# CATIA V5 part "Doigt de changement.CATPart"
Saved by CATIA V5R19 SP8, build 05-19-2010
Part number: Doigt de changement
Bounding box of the stored display mesh (mm): x 0 to 20, y -70.483 to 16.59, z -33.519 to 15
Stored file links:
  F:\CFAO\Hberriche\Doigt de changement.CATPart
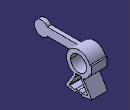
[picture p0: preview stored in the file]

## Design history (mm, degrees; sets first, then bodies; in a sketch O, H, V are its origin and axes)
Body1 (main body)
  Sketch1 on yz-plane, origin (0, 0, 0), H (0, 1, 0), V (0, 0, 1)
    circle A1 centre (0, 0) radius 10
    circle A2 centre (0, 0) radius 15
    radius A1 = 10
    radius A2 = 15
  Pad1: profile Sketch1, direction (1, 0, 0), length 20
  Plane1: type Offset, RefPlane zx-plane, Offset 14
  Sketch2 on Plane1, origin (0, 14, 0), H (-1, 0, 0), V (0, 0, 1)
    point P1 (0, 5)
    line L1 (0, 5) -> (-20, 5)
    line L2 (-20, 5) -> (-20, -5)
    line L3 (-20, -5) -> (0, -5)
    line L4 (0, -5) -> (0, 5)
    reference projected line E1 (-20, -10) -> (-20, 10) from edge [end face of Pad1 | face of Pad1 from Sketch1.A1]
    reference projected line E2 through (0, 0) direction (-1, 0) from axis of face of Pad1 from Sketch1.A2
    length L4 = 10
    distance L1 E2 = 5
    coincidence: P1 V, E1 L2
    horizontal: L1 H, L3 H
    vertical: L2 V, L4 V
  Pad2: profile Sketch2, direction (0, 1, 0), length 2
  Sketch3 on face of Pad2, origin (20, 0, 0), H (0, 1, 0), V (0, 0, 1)
    point P1 (-6.4761, -11.7933)
    line L1 (-6.4761, -11.7933) -> (-6.4761, -14.6103)
    point P2 (-6.4761, -14.6103)
    line L2 (-6.4761, -14.6103) -> (-16.5902, -31.3039)
    point P3 (-16.5902, -31.3039)
    axis line L3 (0, 20.9659) -> (0, -37.2678)
    point P4 (0, 20.9659)
    point P5 (0, -37.2678)
    line L4 (-6.4761, -11.7933) -> (0, -11.7933)
    point P6 (0, -11.7933)
    line L5 (-16.5902, -31.3039) -> (-5.1041, -33.5191)
    point P7 (-5.1041, -33.5191)
    arc A1 centre (0, -37.4647) radius 6.4513 from (0, -31.0134) to (-5.1041, -33.5191) ccw
    point P8 (0, -37.4647)
    point P9 (-5.1041, -33.5191)
    point P10 (0, -31.0134)
    point P11 (6.4761, -11.7933)
    point P12 (6.4761, -14.6103)
    point P13 (16.5902, -31.3039)
    point P14 (0, -37.2678)
    point P15 (0, -11.7933)
    point P16 (5.1041, -33.5191)
    point P18 (5.1041, -33.5191)
    point P19 (0, -31.0134)
    line L6 (6.4761, -11.7933) -> (6.4761, -14.6103)
    line L7 (6.4761, -14.6103) -> (16.5902, -31.3039)
    line L8 (6.4761, -11.7933) -> (0, -11.7933)
    line L9 (16.5902, -31.3039) -> (5.1041, -33.5191)
    arc A2 centre (0, -37.4647) radius 6.4513 from (0, -31.0134) to (5.1041, -33.5191) cw
    vertical: L1 V, L3 V
    coincidence: P4 V, P6 L3, P9 L5, P10 L3, P7 P9, P8 L3, P6 P15, P10 P19, P16 P18
    horizontal: L4 H
    symmetry: P1 P11 L3, P2 P12 L3, P3 P13 L3, P5 P14 L3, P6 P15 L3, P7 P16 L3, P9 P18 L3, P10 P19 L3, L1 L6 L3, L2 L7 L3, L4 L8 L3, L5 L9 L3, A1 A2 L3
  Pad3: profile Sketch3, direction (-1, 0, 0), length 20
  Sketch4 on face of Pad3, origin (20, 0, 0), H (0, 1, 0), V (0, 0, 1)
    axis line L1 (0, -45.8809) -> (0, -7.9795)
    point P1 (0, -45.8809)
    point P2 (0, -7.9795)
    line L2 (0, -12.3129) -> (-3, -12.3129)
    point P3 (0, -12.3129)
    point P4 (-4, -12.3129)
    line L3 (-4, -13.3129) -> (-4, -14.9164)
    point P5 (-4, -16.3129)
    line L4 (-4.7236, -17.5073) -> (-11.42, -28.5599)
    line L5 (-11.0871, -29.31) -> (-4.6321, -30.5548)
    point P6 (-4.6321, -30.5548)
    arc A1 centre (0, -37.7651) radius 8.57 from (0, -29.1951) to (-4.6321, -30.5548) ccw
    point P7 (0, -37.7651)
    point P8 (0, -29.1951)
    reference projected line E1 (-6.4761, -14.6103) -> (-16.5902, -31.3039) from edge [face of Pad3 from Sketch3.L2 | start face of Pad3]
    reference projected line E2 (-16.5902, -31.3039) -> (-5.1041, -33.5191) from edge [face of Pad3 from Sketch3.L5 | start face of Pad3]
    arc A2 centre (-10.9924, -28.819) radius 0.5 from (-11.42, -28.5599) to (-11.0871, -29.31) ccw
    point P9 (-11.42, -28.5599)
    point P10 (-11.0871, -29.31)
    arc A3 centre (-3, -13.3129) radius 1 from (-4, -13.3129) to (-3, -12.3129) cw
    point P12 (-4, -13.3129)
    point P13 (-3, -12.3129)
    arc A4 centre (-9, -14.9164) radius 5 from (-4, -14.9164) to (-4.7236, -17.5073) cw
    point P15 (-4, -14.9164)
    point P16 (-4.7236, -17.5073)
    point P18 (0, -7.9795)
    point P19 (0, -12.3129)
    point P20 (4, -12.3129)
    point P21 (4, -16.3129)
    point P22 (4.6321, -30.5548)
    point P24 (0, -29.1951)
    point P25 (11.42, -28.5599)
    point P26 (11.0871, -29.31)
    point P28 (4, -13.3129)
    point P29 (3, -12.3129)
    point P31 (4, -14.9164)
    point P32 (4.7236, -17.5073)
    line L6 (0, -12.3129) -> (3, -12.3129)
    line L7 (4, -13.3129) -> (4, -14.9164)
    line L8 (4.7236, -17.5073) -> (11.42, -28.5599)
    line L9 (11.0871, -29.31) -> (4.6321, -30.5548)
    arc A5 centre (0, -37.7651) radius 8.57 from (0, -29.1951) to (4.6321, -30.5548) cw
    arc A6 centre (10.9924, -28.819) radius 0.5 from (11.42, -28.5599) to (11.0871, -29.31) cw
    arc A7 centre (3, -13.3129) radius 1 from (4, -13.3129) to (3, -12.3129) ccw
    arc A8 centre (9, -14.9164) radius 5 from (4, -14.9164) to (4.7236, -17.5073) ccw
    distance E1 L4 = 3
    distance E2 L5 = 3
    radius A2 = 0.5
    distance P4 P5 = 4
    distance P3 P4 = 4
    radius A3 = 1
    radius A4 = 5
    coincidence: P1 V, P3 L1, P7 L1, P8 L1, L3 P4, L2 P4, L3 P5, L4 P5, P3 P19, P8 P24
    vertical: L1 V, L3 V
    horizontal: L2 H
    tangency: A2 L4, A2 L5, A3 L3, A3 L2, A4 L3, A4 L4
    symmetry: P2 P18 L1, P3 P19 L1, P4 P20 L1, P5 P21 L1, P6 P22 L1, P8 P24 L1, P9 P25 L1, P10 P26 L1, P12 P28 L1, P13 P29 L1, P15 P31 L1, P16 P32 L1, L2 L6 L1, L3 L7 L1, L4 L8 L1, L5 L9 L1, A1 A5 L1, A2 A6 L1, A3 A7 L1, A4 A8 L1
  Pocket1: profile Sketch4, direction (-1, 0, 0), through (limit type 3)
  Plane2: type Offset, RefPlane zx-plane, Offset 14, reversed
  Sketch5 on Plane2, origin (0, -14, 0), H (-1, 0, 0), V (0, 0, 1)
    point P1 (0, 5)
    line L1 (0, 5) -> (-5, 5)
    line L2 (-5, 5) -> (-5, -5)
    line L3 (-5, -5) -> (0, -5)
    line L4 (0, -5) -> (0, 5)
    reference projected line E1 through (0, 0) direction (-1, 0) from axis of face of Pad1 from Sketch1.A2
    length L2 = 10
    distance E1 L1 = 5
    length L3 = 5
    coincidence: P1 V
    horizontal: L1 H, L3 H
    vertical: L2 V, L4 V
  Pad4: profile Sketch5, direction (0, -1, 0), length 40
  Sketch6 on face of Pad4 from Sketch5.L2, origin (5, 0, 0), H (0, 1, 0), V (0, 0, 1)
    axis line L1 (-95.4167, 0) -> (-31.4362, 0)
    point P1 (-95.4167, 0)
    line L2 (-54, 0) -> (-54, -5)
    point P3 (-54, 0)
    point P4 (-54, -5)
    reference projected line E1 (-54, 5) -> (-54, -5) from edge [end face of Pad4 | face of Pad4 from Sketch5.L2]
    reference projected line E2 (-14, -5) -> (-64, -5) from edge [face of Pad4 from Sketch5.L2 | face of Pad4 from Sketch5.L3]
    line L3 (-70.4833, 0) -> (-70.4833, 0)
    point P5 (-70.4833, 0)
    point P6 (-70.4833, 0)
    arc A1 centre (-61.4833, 0) radius 9 from (-54, -5) to (-70.4833, 0) cw
    point P7 (-61.4833, 0)
    point P8 (-54, 0)
    point P9 (-54, 5)
    point P10 (-70.4833, 0)
    point P11 (-70.4833, 0)
    line L4 (-54, 0) -> (-54, 5)
    line L5 (-70.4833, 0) -> (-70.4833, 0)
    arc A2 centre (-61.4833, 0) radius 9 from (-54, 5) to (-70.4833, 0) ccw
    radius A1 = 9
    coincidence: P1 H, P3 L1, E1 L2, E2 P4, P5 L1, A1 P5, P7 L1, P3 P8
    horizontal: L1 H
    vertical: L2 V, L3 V
    symmetry: P3 P8 L1, P4 P9 L1, P5 P10 L1, P6 P11 L1, L2 L4 L1, L3 L5 L1, A1 A2 L1
  Pad5: profile Sketch6, direction (-1, 0, 0), length 5
  Sketch7 on face of Pad5, origin (5, 0, 0), H (0, 1, 0), V (0, 0, 1)
    arc A1 centre (-61.4833, 0) radius 9 from (-54, -5) to (-70.4833, 0) cw
    point P2 (-70.4833, 0)
    point P3 (-54, -5)
    reference projected arc E1 centre (-61.4833, 0) radius 9 from (-70.4833, 0) to (-54, -5) ccw from edge [face of Pad5 from Sketch6.A1 | face of Pad5]
    reference projected point E2 (-54, -5) from vertex [face of Pad4 from Sketch5.L3 | face of Pad5 | face of Pad5 from Sketch6.A1]
    point P4 (-61.4833, -9)
    coincidence: P2 H, E2 P3, P4 A1
    concentricity: E1 A1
